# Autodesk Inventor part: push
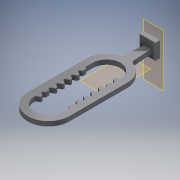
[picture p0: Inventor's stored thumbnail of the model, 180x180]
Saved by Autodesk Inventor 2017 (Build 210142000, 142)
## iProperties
Created: 2017-05
Part Number: push
Material: Generic
Document SubType Name: Modeling
Designer: 1717440
Density: 1 g/cm^3
Appearance: Default
Author: 1717440
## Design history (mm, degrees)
workplane "Work Plane1"
sketch "Sketch1"
  geometry: L1 (0, 3.175)-(17, 3.175) reference; L2 (17, 3.175)-(0, 3.175); L3 (0, 3.175)-(0, 20.175); L4 (0, 20.175)-(17, 20.175); L5 (17, 20.175)-(17, 3.175); 1 further point
  constraints: 8 end point, 2 parallel, 1 horizontal, 1 perpendicular
  dimensions: "d0" = 17 distance of L2.end L3.end
extrude "Extrusion1" new body sketch "Sketch1" distance "d1" = 5; taper "d2" = 0 deg
workplane "Work Plane2"
sketch "Sketch2" dims "d68" = 10, "d80" = 10
  geometry: L1 (-38.705, -3.689)-(1.295, -3.689); L2 (-18.705, -3.689)-(-18.705, 6.001); L3 (-39.255, -7.416)-(-39.255, 0.038); L4 (68.82, -3.689)-(5.82, -3.689); L5 (68.82, 11.311)-(5.82, 11.311); L6 (5.82, -18.689)-(68.82, -18.689); L7 (5.82, 11.311)-(8.32, 6.981); L8 (5.82, 11.311)-(10.82, 11.311); L9 (8.32, 6.981)-(9.82, 6.981); L10 (9.82, 6.981)-(12.32, 11.311); L11 (5.82, 11.311)-(12.32, 11.311); L12 (13.92, 11.311)-(16.42, 6.981); L13 (16.42, 6.981)-(17.92, 6.981); L14 (17.92, 6.981)-(20.42, 11.311); L15 (13.92, 11.311)-(20.42, 11.311); L16 (22.02, 11.311)-(24.52, 6.981); L17 (24.52, 6.981)-(26.02, 6.981); L18 (26.02, 6.981)-(28.52, 11.311); L19 (22.02, 11.311)-(28.52, 11.311); L20 (30.12, 11.311)-(32.62, 6.981); L21 (32.62, 6.981)-(34.12, 6.981); L22 (34.12, 6.981)-(36.62, 11.311); L23 (30.12, 11.311)-(36.62, 11.311); L24 (38.22, 11.311)-(40.72, 6.981); L25 (40.72, 6.981)-(42.22, 6.981); L26 (42.22, 6.981)-(44.72, 11.311); L27 (38.22, 11.311)-(44.72, 11.311); L28 (46.32, 11.311)-(48.82, 6.981); L29 (48.82, 6.981)-(50.32, 6.981); L30 (50.32, 6.981)-(52.82, 11.311); L31 (46.32, 11.311)-(52.82, 11.311); L32 (15.17, 9.146)-(19.17, 9.146); L33 (54.42, 11.311)-(56.92, 6.981); L34 (56.92, 6.981)-(58.42, 6.981); L35 (58.42, 6.981)-(60.92, 11.311); L36 (54.42, 11.311)-(60.92, 11.311); L37 (59.67, 9.146)-(55.67, 9.146); L38 (13.82, -18.689)-(16.32, -14.359); L39 (13.82, -18.689)-(18.82, -18.689); L40 (16.32, -14.359)-(17.82, -14.359); L41 (17.82, -14.359)-(20.32, -18.689); L42 (13.82, -18.689)-(20.32, -18.689); L43 (21.82, -18.689)-(28.32, -18.689); L44 (25.82, -14.359)-(28.32, -18.689); L45 (24.32, -14.359)-(25.82, -14.359); L46 (21.82, -18.689)-(24.32, -14.359); L47 (29.82, -18.689)-(36.32, -18.689); L48 (33.82, -14.359)-(36.32, -18.689); L49 (32.32, -14.359)-(33.82, -14.359); L50 (29.82, -18.689)-(32.32, -14.359); L51 (37.82, -18.689)-(44.32, -18.689); L52 (41.82, -14.359)-(44.32, -18.689); L53 (40.32, -14.359)-(41.82, -14.359); L54 (37.82, -18.689)-(40.32, -14.359); L55 (45.82, -18.689)-(52.32, -18.689); L56 (49.82, -14.359)-(52.32, -18.689); L57 (48.32, -14.359)-(49.82, -14.359); L58 (45.82, -18.689)-(48.32, -14.359); L59 (53.82, -18.689)-(60.32, -18.689); L60 (57.82, -14.359)-(60.32, -18.689); L61 (56.32, -14.359)-(57.82, -14.359); L62 (53.82, -18.689)-(56.32, -14.359); L63 (61.82, -18.689)-(68.32, -18.689); L64 (65.82, -14.359)-(68.32, -18.689)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; A1 r 15 centre (68.82, -3.689) between (68.82, -18.689) and (68.82, 11.311); A2 r 15 centre (5.82, -3.689) between (5.82, 11.311) and (5.82, -18.689); A3 r 22.5 centre (5.82, -3.689) between (-15.485, -10.922) and (5.82, -26.189); A4 r 22.5 centre (68.82, -3.689) between (68.82, -26.189) and (68.82, 18.811); A5 r 3 centre (-18.326, -11.887) between (-15.485, -10.922) and (-18.117, -8.894); A6 r 3 centre (-18.326, 4.509) between (-18.117, 1.516) and (-15.485, 3.545); A7 r 22.5 centre (5.82, -3.689) between (5.82, 18.811) and (-15.485, 3.545); 5 further points
  constraints: 154 end point, 17 point on circle, 10 horizontal, 10 midpoint, 7 centre point, 6 tangent, 5 point on line, 4 symmetric about line, 3 equal length, 2 collinear, 2 parallel, 1 perpendicular, 1 vertical, 101 other
  dimensions: "d45" = 30 diameter of A2; "d46" = 93 distance of point (83.82, -3.689) point (-9.18, -3.689); "d47" = 40 distance of L1.start L1.end; "d54" = 7.45397 distance of L3.start L3.end; "d59" = 5 distance of L5.end L7.end; "d60" = 60 deg angle of L7 L8; "d61" = 1.5 distance of L7.end L9.end; "d62" = 120 deg angle of L10 L9; "d65" = 8.1 distance of L5.end L12.start; "d70" = 5 distance of L38.start L38.end; "d71" = 60 deg angle of L39 L38; "d72" = 8 distance of L6.start L38.start; "d73" = 1.5 distance of L38.end L40.end; "d74" = 120 deg angle of L40 L41; "d77" = 8 distance of L38.start L43.start; "d82" = 7.5 radial gap between concentric circles of A1 A4; "d83" = 28 distance of L3.start L75.end; "d84" = 4 deg angle of L71 L72; "d85" = 28 distance of L3.end L75.start; "d86" = 4 deg angle of L74 L73; "d87" = 3 radius of A5 (derived)
extrude "Extrusion6" join sketch "Sketch2" distance "d88" = 5; taper "d89" = 0 deg
sketch "Sketch3"
  geometry: L1 (-3.689, -68.82)-(-3.689, -5.82); L2 (7.416, -74.703)-(-14.794, -74.703); L3 (-14.794, -74.703)-(-14.794, 0.062); L4 (-14.794, 0.062)-(7.416, 0.062); L5 (7.416, 0.062)-(7.416, -74.703); L6 (7.416, -74.703)-(-14.794, 0.062); L7 (-14.794, -74.703)-(7.416, 0.062); A1 r 15 centre (-3.689, -5.82) between (11.311, -5.82) and (-18.689, -5.82) reference; A2 r 15 centre (-3.689, -68.82) between (-18.689, -68.82) and (11.311, -68.82) reference; 2 further points
  constraints: 14 end point, 3 midpoint, 2 parallel, 1 horizontal, 1 perpendicular, 1 vertical
extrude "Extrusion7" cut sketch "Sketch3" stored distance "d90" = 0; taper "d91" = 0 deg
sketch "Sketch4"
  geometry: L1 (7.416, -48.569)-(7.416, -50.572) reference; L2 (7.416, -50.572)-(11.311, -52.82) reference; L3 (11.311, -52.82)-(11.311, -54.42) reference; L4 (11.311, -54.42)-(9.146, -55.67) reference; L5 (9.146, -55.67)-(9.146, -59.67) reference; L6 (9.146, -59.67)-(11.311, -60.92) reference; L7 (-18.689, -68.32)-(-14.794, -66.072) reference; L8 (-14.794, -66.072)-(-14.794, -64.069) reference; L9 (-14.794, -64.069)-(-18.689, -61.82) reference; L10 (-18.689, -61.82)-(-18.689, -60.32) reference; L11 (-18.689, -60.32)-(-16.524, -59.07) reference; L12 (-16.524, -59.07)-(-16.524, -55.07) reference; L13 (-16.524, -55.07)-(-18.689, -53.82) reference; L14 (-18.689, -53.82)-(-18.689, -52.32) reference; L15 (-18.689, -52.32)-(-14.794, -50.072) reference; L16 (-14.794, -50.072)-(-14.794, -48.069) reference; L17 (-14.794, -48.069)-(-18.689, -45.82) reference; L18 (-18.689, -45.82)-(-18.689, -44.32) reference; L19 (-18.689, -44.32)-(-14.794, -42.072) reference; L20 (-14.794, -42.072)-(-14.794, -40.069) reference; L21 (-14.794, -40.069)-(-18.689, -37.82) reference; L22 (-18.689, -37.82)-(-18.689, -36.32) reference; L23 (-18.689, -36.32)-(-14.794, -34.072) reference; L24 (-14.794, -34.072)-(-14.794, -32.069) reference; L25 (-14.794, -32.069)-(-18.689, -29.82) reference; L26 (-18.689, -29.82)-(-18.689, -28.32) reference; L27 (-18.689, -28.32)-(-14.794, -26.072) reference; L28 (-14.794, -26.072)-(-14.794, -24.069) reference; L29 (-14.794, -24.069)-(-18.689, -21.82) reference; L30 (-18.689, -21.82)-(-18.689, -20.32) reference; L31 (-18.689, -20.32)-(-16.524, -19.07) reference; L32 (-16.524, -19.07)-(-16.524, -15.07) reference; L33 (-16.524, -15.07)-(-18.689, -13.82) reference; L34 (11.311, -5.82)-(7.416, -8.069) reference; L35 (7.416, -8.069)-(7.416, -10.072) reference; L36 (7.416, -10.072)-(11.311, -12.32) reference; L37 (11.311, -12.32)-(11.311, -13.92) reference; L38 (11.311, -13.92)-(9.146, -15.17) reference; L39 (9.146, -15.17)-(9.146, -19.17) reference; L40 (9.146, -19.17)-(11.311, -20.42) reference; L41 (11.311, -20.42)-(11.311, -22.02) reference; L42 (11.311, -22.02)-(7.416, -24.269) reference; L43 (7.416, -24.269)-(7.416, -26.272) reference; L44 (7.416, -26.272)-(11.311, -28.52) reference; L45 (11.311, -28.52)-(11.311, -30.12) reference; L46 (11.311, -30.12)-(7.416, -32.369) reference; L47 (7.416, -32.369)-(7.416, -34.372) reference; L48 (7.416, -34.372)-(11.311, -36.62) reference; L49 (11.311, -36.62)-(11.311, -38.22) reference; L50 (11.311, -38.22)-(7.416, -40.469) reference; L51 (7.416, -40.469)-(7.416, -42.472) reference; L52 (7.416, -42.472)-(11.311, -44.72) reference; L53 (11.311, -44.72)-(11.311, -46.32) reference; L54 (11.311, -46.32)-(7.416, -48.569) reference; L55 (-18.689, -68.32)-(-18.689, -68.82) reference; L56 (-3.689, -68.82)-(-18.689, -68.32); L57 (-18.689, -5.82)-(-18.689, -13.82) reference; L58 (-18.689, -68.32)-(-18.689, -5.82); L59 (-18.689, -5.82)-(11.311, -5.82); L60 (11.311, -68.82)-(11.311, -60.92) reference; L61 (-3.689, -68.82)-(11.311, -68.82); L62 (11.311, -68.82)-(11.311, -5.82); A1 r 22.5 centre (-3.689, -68.82) between (-26.189, -68.82) and (18.811, -68.82) reference; 1 further point
  constraints: 10 end point, 2 perpendicular, 1 collinear, 1 horizontal
extrude "Extrusion8" cut sketch "Sketch4" distance "d92" = 10; taper "d93" = 0 deg
sketch "Sketch5"
  geometry: L1 (-7.454, 38.705)-(0.077, 38.705) reference; L2 (-7.454, 38.705)-(-8.894, 18.117) reference; L3 (-26.189, -5.82)-(-26.189, -68.82) reference; L4 (18.811, -68.82)-(18.811, -5.82) reference; L5 (1.516, 18.117)-(0.077, 38.705) reference; L6 (-18.689, -68.82)-(-18.689, -5.82) reference; L7 (11.311, -5.82)-(11.311, -68.82) reference; A1 r 3 centre (-11.887, 18.326) between (-10.922, 15.485) and (-8.894, 18.117) reference; A2 r 22.5 centre (-3.689, -5.82) between (-10.922, 15.485) and (-26.189, -5.82) reference; A3 r 22.5 centre (-3.689, -68.82) between (-26.189, -68.82) and (18.811, -68.82) reference; A4 r 22.5 centre (-3.689, -5.82) between (18.811, -5.82) and (3.545, 15.485) reference; A5 r 3 centre (4.509, 18.326) between (1.516, 18.117) and (3.545, 15.485) reference; A6 r 15 centre (-3.689, -5.82) between (11.311, -5.82) and (-18.689, -5.82) reference; A7 r 15 centre (-3.689, -68.82) between (-18.689, -68.82) and (11.311, -68.82) reference; 1 further point
sketch "Sketch6"
  geometry: L1 (-18.689, -68.82)-(-18.689, -5.82) reference; L2 (11.311, -5.82)-(11.311, -68.82) reference; L3 (-18.689, -37.32)-(-12.468, -37.32); L4 (-18.689, -37.32)-(-14.613, -37.32); L5 (-14.613, -37.32)-(-14.613, -36.659); L6 (-14.613, -36.659)-(-18.689, -35.676); L7 (-18.689, -5.82)-(-18.689, -68.82) reference; A1 r 15 centre (-3.689, -5.82) between (11.311, -5.82) and (-18.689, -5.82) reference; A2 r 15 centre (-3.689, -68.82) between (-18.689, -68.82) and (11.311, -68.82) reference; 1 further point
  constraints: 8 end point, 2 point on line, 1 horizontal, 1 midpoint, 1 vertical
extrude "Extrusion9" join sketch "Sketch6" stored distance "d94" = 10; taper "d95" = 0 deg
mirror "Mirror1"
pattern_linear "Rectangular Pattern1" dims "d98" = 5.5
sketch "Sketch7"
  geometry: L1 (-7.454, 38.705)-(0.077, 38.705) reference; L2 (-7.454, 38.705)-(-8.894, 18.117) reference; L3 (-26.189, -5.82)-(-26.189, -68.82) reference; L4 (18.811, -68.82)-(18.811, -5.82) reference; L5 (1.516, 18.117)-(0.077, 38.705) reference; L6 (-18.689, -68.82)-(-18.689, -55.464) reference; L7 (-14.613, -54.481)-(-18.689, -55.464) reference; L8 (-14.613, -54.481)-(-14.613, -53.159) reference; L9 (-14.613, -53.159)-(-18.689, -52.176) reference; L10 (-18.689, -52.176)-(-18.689, -49.964) reference; L11 (-14.613, -48.981)-(-18.689, -49.964) reference; L12 (-14.613, -48.981)-(-14.613, -47.659) reference; L13 (-14.613, -47.659)-(-18.689, -46.676) reference; L14 (-18.689, -46.676)-(-18.689, -44.464) reference; L15 (-14.613, -43.481)-(-18.689, -44.464) reference; L16 (-14.613, -43.481)-(-14.613, -42.159) reference; L17 (-14.613, -42.159)-(-18.689, -41.176) reference; L18 (-18.689, -41.176)-(-18.689, -38.964) reference; L19 (-14.613, -37.981)-(-18.689, -38.964) reference; L20 (-14.613, -37.981)-(-14.613, -36.659) reference; L21 (-14.613, -36.659)-(-18.689, -35.676) reference; L22 (-18.689, -35.676)-(-18.689, -33.464) reference; L23 (-14.613, -32.481)-(-18.689, -33.464) reference; L24 (-14.613, -32.481)-(-14.613, -31.159) reference; L25 (-14.613, -31.159)-(-18.689, -30.176) reference; L26 (-18.689, -30.176)-(-18.689, -27.964) reference; L27 (-14.613, -26.981)-(-18.689, -27.964) reference; L28 (-14.613, -26.981)-(-14.613, -25.659) reference; L29 (-14.613, -25.659)-(-18.689, -24.676) reference; L30 (-18.689, -24.676)-(-18.689, -22.464) reference; L31 (-14.613, -21.481)-(-18.689, -22.464) reference; L32 (-14.613, -21.481)-(-14.613, -20.159) reference; L33 (-14.613, -20.159)-(-18.689, -19.176) reference; L34 (-18.689, -19.176)-(-18.689, -5.82) reference; L35 (11.311, -5.82)-(11.311, -68.82) reference; L36 (-3.689, -68.82)-(-3.689, -5.82); A1 r 3 centre (-11.887, 18.326) between (-10.922, 15.485) and (-8.894, 18.117) reference; A2 r 22.5 centre (-3.689, -5.82) between (-10.922, 15.485) and (-26.189, -5.82) reference; A3 r 22.5 centre (-3.689, -68.82) between (-26.189, -68.82) and (18.811, -68.82) reference; A4 r 22.5 centre (-3.689, -5.82) between (18.811, -5.82) and (3.545, 15.485) reference; A5 r 3 centre (4.509, 18.326) between (1.516, 18.117) and (3.545, 15.485) reference; A6 r 15 centre (-3.689, -5.82) between (11.311, -5.82) and (-18.689, -5.82) reference; A7 r 15 centre (-3.689, -68.82) between (-18.689, -68.82) and (11.311, -68.82) reference; 4 further points
  constraints: 2 end point, 1 coincident, 1 midpoint, 1 vertical
  dimensions: "d99" = 2.212 distance of L18.end L17.end (derived); "d100" = 1.106 vertical distance of point (-3.689, -37.32) point (-3.727, -38.426) (= 0.5 x d99)
workaxis "Work Axis1"
pattern_circular "Circular Pattern1" dims angle "d102" = 360 deg
sketch "Sketch8"
  geometry: L1 (-14.613, -48.981)-(-18.689, -49.964) reference; L2 (-14.613, -48.981)-(-14.613, -47.659) reference; L3 (-14.613, -47.659)-(-18.689, -46.676) reference; L4 (-14.613, -21.481)-(-14.613, -20.159) reference; L5 (-14.613, -20.159)-(-18.689, -19.176) reference; L6 (-17.241, -49.615)-(-16.651, -47.168); L7 (-18.689, -22.464)-(-14.613, -21.481) reference; L8 (-17.241, -22.115)-(-17.241, -19.526); 1 further point
  constraints: 4 end point, 3 point on line, 1 midpoint, 1 vertical
extrude "Extrusion10" cut sketch "Sketch8" distance "d104" = 10; taper "d105" = 0 deg
pattern_circular "Circular Pattern2" dims angle "d107" = 360 deg
body "Solid1"
node "Reference1"
